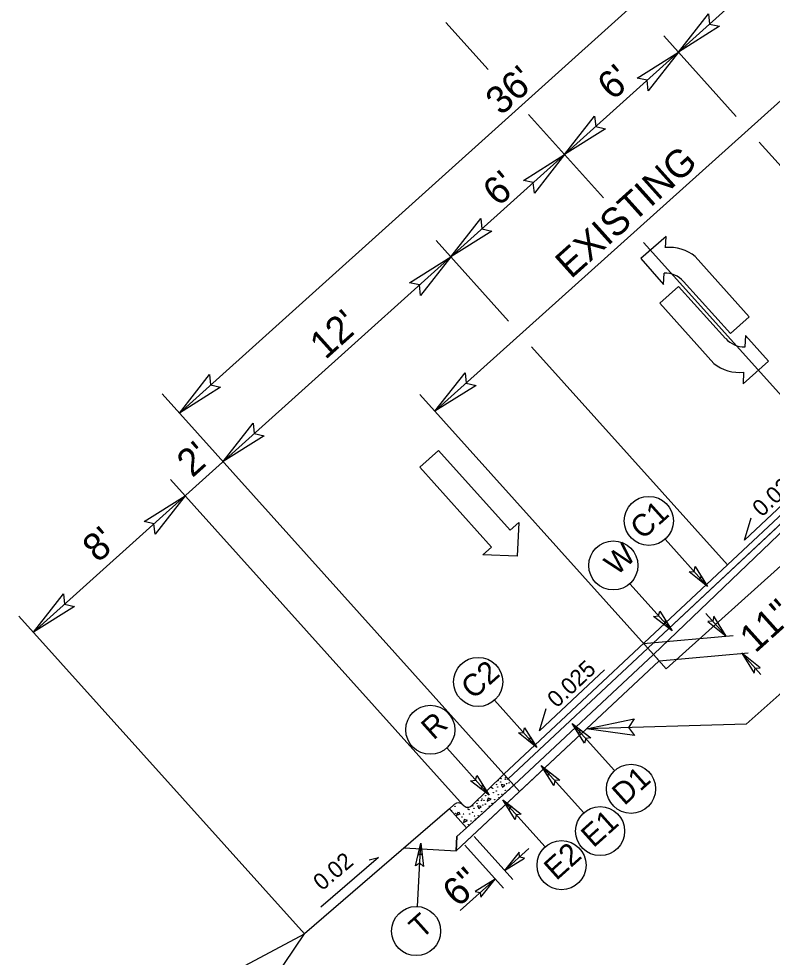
# Model space of a CAD drawing. Extents: x 2488411 to 2488707, y 383669 to 383962.
# Drawn here: x 2488415.07 to 2488444.6, y 383707.76 to 383744.52 of the extents above; entities that cross this region are included whole.
import ezdxf

# ---------------------------------------------------------------- set-up
doc = ezdxf.new("R2010")
doc.units = 0
for name, color, linetype in [('Old_Level_44', 7, 'Continuous'), ('Prop Dimension', 7, 'Continuous'), ('Prop DSN Text', 7, 'Continuous'), ('Prop Paint Stripe', 7, 'Continuous'), ('Prop PFL Text', 7, 'Continuous'), ('Prop Rip Rap Related Quantities Text', 7, 'Continuous'), ('Prop Roadway Bridge', 7, 'Continuous'), ('Prop Roadway Profile Bench Mark Info Text', 7, 'Continuous'), ('Prop ROW RW Lines', 7, 'Continuous'), ('Prop Vertical Profile Curve Label', 7, 'Continuous'), ('Sheet Data Field CELL', 7, 'Continuous'), ('Sheet Sticker Preliminary CELL', 7, 'Continuous'), ('Sheet Symbology CELL', 7, 'Continuous'), ('Sheet Title CELL', 7, 'Continuous'), ('Typical ID Circle CELL', 7, 'Continuous'), ('Typical Terminator CELL', 7, 'Continuous'), ('Typical Text General CELL', 7, 'Continuous'), ('Typical Text ID Circle CELL', 7, 'Continuous')]:
    doc.layers.add(name, color=color, linetype=linetype)

msp = doc.modelspace()

# ---------------------------------------------------------------- linework, layer by layer
at = {"layer": 'Prop Dimension'}
for q in [(2488444.986, 383718.147), (2488437.318, 383716.711)]:
    msp.add_line((2488443.582, 383716.885), q, dxfattribs=at)
at = {"layer": 'Prop DSN Text'}
for p, q in [((2488440.407, 383724.137), (2488442.069, 383722.289)), ((2488439.017, 383722.394), (2488440.679, 383720.545)), ((2488433.72, 383717.83), (2488435.381, 383715.981)), ((2488438.426, 383715.072), (2488436.764, 383716.92)), ((2488431.845, 383715.958), (2488433.506, 383714.109)), ((2488437.214, 383713.418), (2488435.552, 383715.266)), ((2488435.704, 383712.085), (2488434.043, 383713.933)), ((2488430.695, 383709.748), (2488430.828, 383712.23))]:
    msp.add_line(p, q, dxfattribs=at)
for centre in [(2488439.765, 383724.852), (2488438.374, 383723.109), (2488433.077, 383718.545), (2488431.202, 383716.673), (2488439.068, 383714.357), (2488437.856, 383712.703), (2488436.347, 383711.369), (2488430.645, 383708.788)]:
    msp.add_circle(centre, 0.962, dxfattribs=at)
at = {"layer": 'Prop Paint Stripe'}
for points in [[(2488441.583, 383723.062), (2488442.069, 383722.289), (2488441.345, 383722.855), (2488441.541, 383722.876)], [(2488440.192, 383721.318), (2488440.679, 383720.545), (2488439.955, 383721.111), (2488440.151, 383721.133)], [(2488442.082, 383720.909), (2488442.798, 383720.343), (2488442.312, 383721.123), (2488442.27, 383720.93)], [(2488444.124, 383719.1), (2488443.407, 383719.666), (2488443.893, 383718.886), (2488443.935, 383719.078)], [(2488434.895, 383716.754), (2488435.381, 383715.981), (2488434.657, 383716.547), (2488434.853, 383716.569)], [(2488437.25, 383716.147), (2488436.764, 383716.92), (2488437.488, 383716.354), (2488437.292, 383716.332)], [(2488436.038, 383714.493), (2488435.552, 383715.266), (2488436.276, 383714.7), (2488436.08, 383714.679)], [(2488433.02, 383714.882), (2488433.506, 383714.109), (2488432.782, 383714.675), (2488432.978, 383714.697)], [(2488434.529, 383713.16), (2488434.043, 383713.933), (2488434.767, 383713.367), (2488434.571, 383713.345)], [(2488430.625, 383711.339), (2488430.828, 383712.23), (2488430.939, 383711.318), (2488430.786, 383711.441)], [(2488434.682, 383711.877), (2488434.116, 383711.16), (2488434.896, 383711.646), (2488434.703, 383711.688)], [(2488433.178, 383710.109), (2488433.744, 383710.826), (2488432.964, 383710.34), (2488433.157, 383710.298)]]:
    msp.add_lwpolyline(points, close=True, dxfattribs=at)
at = {"layer": 'Prop PFL Text'}
for p, q in [((2488429.166, 383711.668), (2488426.917, 383709.729)), ((2488428.81, 383711.571), (2488429.166, 383711.668))]:
    msp.add_line(p, q, dxfattribs=at)
at = {"layer": 'Prop Rip Rap Related Quantities Text'}
for p, q in [((2488439.725, 383719.867), (2488447.397, 383727.046)), ((2488442.847, 383723.13), (2488447.226, 383727.229)), ((2488434.086, 383714.933), (2488442.847, 383723.13)), ((2488434.253, 383714.747), (2488439.725, 383719.867)), ((2488434.474, 383714.501), (2488439.946, 383719.622)), ((2488439.946, 383719.622), (2488439.725, 383719.867)), ((2488432.215, 383711.936), (2488440.166, 383719.376)), ((2488434.476, 383714.499), (2488434.694, 383714.256)), ((2488432.617, 383712.828), (2488432.245, 383712.494)), ((2488432.215, 383711.936), (2488432.245, 383712.494)), ((2488430.177, 383712.044), (2488432.215, 383711.936))]:
    msp.add_line(p, q, dxfattribs=at)
at = {"layer": 'Prop Roadway Bridge'}
for p, q in [((2488439.725, 383719.867), (2488434.253, 383714.747)), ((2488434.474, 383714.501), (2488439.946, 383719.622)), ((2488439.946, 383719.622), (2488439.725, 383719.867)), ((2488434.253, 383714.747), (2488434.474, 383714.501))]:
    msp.add_line(p, q, dxfattribs=at)
at = {"layer": 'Prop Roadway Profile Bench Mark Info Text'}
for p, q in [((2488443.509, 383724.104), (2488446.068, 383726.498)), ((2488443.509, 383724.104), (2488443.775, 383724.979)), ((2488435.475, 383716.626), (2488438.034, 383719.02)), ((2488435.475, 383716.626), (2488435.741, 383717.501))]:
    msp.add_line(p, q, dxfattribs=at)
at = {"layer": 'Prop ROW RW Lines'}
for p, q in [((2488440.444, 383735.998), (2488439.452, 383735.127)), ((2488440.42, 383735.553), (2488440.444, 383735.998)), ((2488439.452, 383735.127), (2488440.343, 383734.113)), ((2488443.696, 383732.851), (2488441.58, 383735.205)), ((2488440.343, 383734.113), (2488440.367, 383734.558)), ((2488440.934, 383734.039), (2488440.198, 383733.377)), ((2488442.769, 383731.997), (2488440.934, 383734.039)), ((2488441.125, 383734.23), (2488442.96, 383732.189)), ((2488440.198, 383733.377), (2488442.314, 383731.023)), ((2488442.96, 383732.189), (2488443.696, 383732.851)), ((2488443.551, 383732.115), (2488443.527, 383731.67)), ((2488444.453, 383731.111), (2488443.551, 383732.115)), ((2488443.461, 383730.219), (2488444.453, 383731.111)), ((2488443.474, 383730.675), (2488443.461, 383730.219)), ((2488430.79, 383726.951), (2488431.526, 383727.612)), ((2488431.526, 383727.612), (2488434.334, 383724.489)), ((2488433.598, 383723.827), (2488430.79, 383726.951)), ((2488434.334, 383724.489), (2488434.669, 383724.79)), ((2488434.669, 383724.79), (2488434.609, 383723.465)), ((2488433.263, 383723.526), (2488433.598, 383723.827)), ((2488434.609, 383723.465), (2488433.263, 383723.526))]:
    msp.add_line(p, q, dxfattribs=at)
for centre, radius, start, end in [((2488440.585, 383733.99), 1.576, 50.6299, 95.9416), ((2488440.396, 383733.579), 0.982, 41.9538, 91.612), ((2488443.507, 383732.651), 0.982, 221.9538, 271.612), ((2488443.319, 383732.241), 1.576, 230.6299, 275.9416)]:
    msp.add_arc(centre, radius, start, end, dxfattribs=at)
at = {"layer": 'Prop Vertical Profile Curve Label'}
msp.add_line((2488431.949, 383713.571), (2488426.269, 383708.675), dxfattribs=at)
at = {"layer": 'Sheet Data Field CELL'}
for p, q in [((2488439.725, 383719.867), (2488447.39, 383727.039)), ((2488447.226, 383727.229), (2488442.847, 383723.13)), ((2488442.847, 383723.13), (2488434.086, 383714.933)), ((2488434.253, 383714.747), (2488439.725, 383719.867)), ((2488434.086, 383714.933), (2488434.253, 383714.747))]:
    msp.add_line(p, q, dxfattribs=at)
at = {"layer": 'Sheet Sticker Preliminary CELL'}
for points in [[(2488442.533, 383744.224), (2488440.923, 383743.211), (2488442.102, 383744.719), (2488442.146, 383744.311)], [(2488439.313, 383742.198), (2488440.923, 383743.211), (2488439.744, 383741.703), (2488439.699, 383742.111)], [(2488438.073, 383740.215), (2488436.463, 383739.202), (2488437.642, 383740.71), (2488437.687, 383740.302)], [(2488434.853, 383738.189), (2488436.463, 383739.202), (2488435.284, 383737.694), (2488435.239, 383738.102)], [(2488433.613, 383736.206), (2488432.003, 383735.193), (2488433.182, 383736.701), (2488433.227, 383736.293)], [(2488430.393, 383734.18), (2488432.003, 383735.193), (2488430.824, 383733.685), (2488430.779, 383734.093)], [(2488422.981, 383730.09), (2488421.371, 383729.077), (2488422.55, 383730.585), (2488422.595, 383730.177)], [(2488432.995, 383730.158), (2488431.385, 383729.145), (2488432.564, 383730.653), (2488432.609, 383730.245)], [(2488424.692, 383728.187), (2488423.082, 383727.173), (2488424.261, 383728.682), (2488424.306, 383728.274)], [(2488419.985, 383724.823), (2488421.595, 383725.837), (2488420.416, 383724.328), (2488420.371, 383724.736)], [(2488441.816, 383722.691), (2488442.069, 383722.289), (2488441.692, 383722.583), (2488441.794, 383722.595)], [(2488417.258, 383721.503), (2488415.648, 383720.49), (2488416.827, 383721.998), (2488416.871, 383721.59)], [(2488440.425, 383720.948), (2488440.679, 383720.545), (2488440.302, 383720.84), (2488440.404, 383720.851)], [(2488439.201, 383716.441), (2488437.318, 383716.711), (2488439.194, 383717.097), (2488438.963, 383716.757)], [(2488437.017, 383716.517), (2488436.764, 383716.92), (2488437.141, 383716.625), (2488437.039, 383716.614)], [(2488435.128, 383716.384), (2488435.381, 383715.981), (2488435.004, 383716.276), (2488435.106, 383716.287)], [(2488435.805, 383714.864), (2488435.552, 383715.266), (2488435.929, 383714.971), (2488435.827, 383714.96)], [(2488433.253, 383714.512), (2488433.506, 383714.109), (2488433.129, 383714.404), (2488433.231, 383714.415)], [(2488434.296, 383713.53), (2488434.043, 383713.933), (2488434.42, 383713.638), (2488434.318, 383713.627)], [(2488430.722, 383711.766), (2488430.828, 383712.23), (2488430.886, 383711.755), (2488430.806, 383711.819)]]:
    msp.add_lwpolyline(points, close=True, dxfattribs=at)
at = {"layer": 'Sheet Symbology CELL'}
for p, q in [((2488439.946, 383719.622), (2488447.537, 383726.883)), ((2488439.946, 383719.622), (2488434.474, 383714.501)), ((2488439.725, 383719.867), (2488439.946, 383719.622)), ((2488440.166, 383719.376), (2488439.946, 383719.622)), ((2488434.474, 383714.501), (2488434.476, 383714.499)), ((2488434.476, 383714.499), (2488434.694, 383714.256)), ((2488434.694, 383714.256), (2488434.476, 383714.499)), ((2488432.215, 383711.936), (2488434.694, 383714.256)), ((2488433.379, 383713.512), (2488432.617, 383712.828)), ((2488432.617, 383712.828), (2488432.245, 383712.494)), ((2488432.245, 383712.494), (2488432.215, 383711.936))]:
    msp.add_line(p, q, dxfattribs=at)
for points in [[(2488447.393, 383727.043), (2488447.39, 383727.039), (2488439.725, 383719.867)], [(2488434.694, 383714.256), (2488437.318, 383716.711), (2488440.166, 383719.376)], [(2488434.476, 383714.499), (2488434.316, 383714.355), (2488434.315, 383714.355)], [(2488434.308, 383714.347), (2488433.387, 383713.52), (2488433.387, 383713.52)]]:
    msp.add_lwpolyline(points, dxfattribs=at)
for centre in [(2488434.307, 383714.356), (2488433.379, 383713.52)]:
    msp.add_arc(centre, 0.00802, 270.1633, 353.7444, dxfattribs=at)
at = {"layer": 'Sheet Title CELL'}
for p, q in [((2488415.648, 383720.49), (2488455.792, 383756.578)), ((2488421.371, 383729.077), (2488448.133, 383753.134)), ((2488443.183, 383740.697), (2488440.35, 383743.848)), ((2488431.385, 383729.145), (2488447.002, 383743.184)), ((2488451.766, 383731.149), (2488444.086, 383739.692)), ((2488434.263, 383732.679), (2488431.43, 383735.83)), ((2488442.847, 383723.13), (2488435.166, 383731.674)), ((2488434.086, 383714.933), (2488420.691, 383729.833)), ((2488439.946, 383719.622), (2488430.792, 383729.805)), ((2488432.488, 383713.719), (2488421.022, 383726.474)), ((2488426.269, 383708.675), (2488415.075, 383721.127)), ((2488442.798, 383720.343), (2488442.003, 383721.227)), ((2488439.558, 383720.053), (2488443.076, 383720.368)), ((2488440.166, 383719.376), (2488443.664, 383719.689)), ((2488444.154, 383718.835), (2488443.407, 383719.666)), ((2488434.437, 383710.803), (2488432.924, 383712.487)), ((2488434.066, 383710.468), (2488432.552, 383712.153)), ((2488435.068, 383712.016), (2488434.116, 383711.16)), ((2488433.744, 383710.826), (2488432.378, 383709.598))]:
    msp.add_line(p, q, dxfattribs=at)
at = {"layer": 'Typical ID Circle CELL'}
for p, q in [((2488434.086, 383714.933), (2488432.833, 383713.708)), ((2488434.476, 383714.499), (2488434.086, 383714.933)), ((2488432.617, 383712.828), (2488434.476, 383714.499)), ((2488434.122, 383714.503), (2488433.978, 383714.534)), ((2488433.978, 383714.534), (2488434.028, 383714.427)), ((2488434.028, 383714.427), (2488434.122, 383714.503)), ((2488431.949, 383713.571), (2488432.142, 383713.745)), ((2488432.488, 383713.72), (2488432.48, 383713.727)), ((2488433.193, 383713.667), (2488433.049, 383713.699)), ((2488433.049, 383713.699), (2488433.099, 383713.592)), ((2488433.099, 383713.592), (2488433.193, 383713.667)), ((2488433.464, 383713.997), (2488433.437, 383713.872)), ((2488433.437, 383713.872), (2488433.587, 383713.953)), ((2488433.587, 383713.953), (2488433.464, 383713.997)), ((2488432.617, 383712.828), (2488431.949, 383713.571)), ((2488432.228, 383713.315), (2488432.313, 383713.451)), ((2488432.361, 383713.372), (2488432.228, 383713.315)), ((2488432.313, 383713.451), (2488432.361, 383713.372)), ((2488432.535, 383713.162), (2488432.509, 383713.037)), ((2488432.509, 383713.037), (2488432.658, 383713.118)), ((2488432.658, 383713.118), (2488432.535, 383713.162))]:
    msp.add_line(p, q, dxfattribs=at)
for centre in [(2488433.978, 383714.756), (2488434.161, 383714.799), (2488433.603, 383714.405), (2488433.792, 383714.528), (2488433.839, 383714.433), (2488433.86, 383714.674), (2488433.963, 383714.628), (2488434.142, 383714.736), (2488434.189, 383714.564), (2488434.238, 383714.738), (2488434.291, 383714.594), (2488434.449, 383714.513), (2488433.376, 383714.094), (2488433.432, 383714.212), (2488433.65, 383714.378), (2488433.673, 383714.207), (2488433.786, 383714.27), (2488433.863, 383714.133), (2488434.005, 383714.145), (2488434.143, 383714.3), (2488434.307, 383714.356), (2488432.171, 383713.669), (2488432.863, 383713.693), (2488433.034, 383713.793), (2488433.07, 383713.898), (2488433.213, 383713.901), (2488433.232, 383713.964), (2488433.26, 383713.729), (2488433.309, 383713.903), (2488433.362, 383713.759), (2488433.52, 383713.678), (2488433.623, 383713.794), (2488433.723, 383713.938), (2488433.897, 383714.009), (2488432.032, 383713.498), (2488432.192, 383713.397), (2488432.503, 383713.377), (2488432.675, 383713.569), (2488432.721, 383713.543), (2488432.744, 383713.372), (2488432.857, 383713.435), (2488432.91, 383713.598), (2488432.934, 383713.298), (2488433.077, 383713.31), (2488433.214, 383713.465), (2488433.379, 383713.52), (2488432.447, 383713.259), (2488432.694, 383712.959), (2488432.795, 383713.103), (2488432.968, 383713.174)]:
    msp.add_circle(centre, 0.00802, dxfattribs=at)
for centre, start, end in [((2488432.302, 383713.567), 41.9538, 131.9538), ((2488432.666, 383713.88), 221.9538, 314.3383)]:
    msp.add_arc(centre, 0.24, start, end, dxfattribs=at)
at = {"layer": 'Typical Terminator CELL'}
for p, q in [((2488433.472, 383742.529), (2488431.812, 383744.376)), ((2488437.99, 383737.504), (2488435.05, 383740.774)), ((2488449.23, 383725), (2488439.562, 383735.755))]:
    msp.add_line(p, q, dxfattribs=at)
at = {"layer": 'Typical Text General CELL'}
for p in [(2488417.413, 383703.983), (2488420.802, 383700.574)]:
    msp.add_line(p, (2488426.269, 383708.675), dxfattribs=at)
at = {"layer": 'Typical Text ID Circle CELL'}
for p, q in [((2488440.451, 383719.059), (2488456.069, 383733.098)), ((2488439.946, 383719.622), (2488447.537, 383726.883)), ((2488440.451, 383719.059), (2488439.946, 383719.622))]:
    msp.add_line(p, q, dxfattribs=at)

# ---------------------------------------------------------------- texts
at = {"layer": 'Old_Level_44'}
for s, height, p in [('C1', 0.8608, (2488439.52, 383724.086)), ('W', 0.861, (2488438.503, 383722.678)), ('C2', 0.8608, (2488432.888, 383717.828)), ('R', 0.861, (2488431.33, 383716.242)), ('D1', 0.8608, (2488438.806, 383713.677)), ('E1', 0.8608, (2488437.594, 383712.023)), ('E2', 0.8608, (2488436.14, 383710.74)), ('T', 0.861, (2488430.856, 383708.445))]:
    msp.add_text(s, height=height, rotation=41.9538, dxfattribs=at).set_placement(p)
at = {"layer": 'Prop PFL Text'}
msp.add_text('0.02 ', height=0.6476, rotation=40.1454, dxfattribs=at).set_placement((2488426.955, 383710.339))
at = {"layer": 'Prop Roadway Profile Bench Mark Info Text'}
for p in [(2488444.192, 383724.977), (2488436.158, 383717.499)]:
    msp.add_text('0.025', height=0.6476, rotation=43.0996, dxfattribs=at).set_placement(p)
at = {"layer": 'Sheet Title CELL'}
for s, p in [("36'", (2488433.977, 383740.699)), ("6'", (2488438.358, 383741.287)), ('EXISTING', (2488436.715, 383734.307)), ("6'", (2488433.872, 383737.13)), ("12'", (2488427.09, 383731.141)), ("2'", (2488421.877, 383726.519)), ("8'", (2488418.182, 383723.184)), ('11"', (2488443.935, 383719.647)), ('6"', (2488432.289, 383709.684))]:
    msp.add_text(s, height=1.0817, rotation=41.9538, dxfattribs=at).set_placement(p)

doc.saveas('drawing.dxf')
